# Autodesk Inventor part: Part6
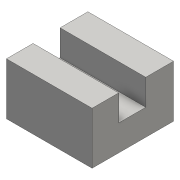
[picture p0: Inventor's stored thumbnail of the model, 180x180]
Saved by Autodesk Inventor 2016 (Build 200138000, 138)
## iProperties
Created: 2015-07
Part Number: Part6
Material: Generic
Document SubType Name: Modeling
Designer: Sandeep
Density: 1 g/cm^3
Appearance: Default
Author: Sandeep
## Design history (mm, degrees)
sketch "Sketch1"
  geometry: L1 (-17.042, 14.133)-(12.609, 14.133); L2 (12.609, 14.133)-(12.609, -14.063); L3 (12.609, -14.063)-(-17.042, -14.063); L4 (-17.042, -14.063)-(-17.042, 14.133); 1 further point
  constraints: 8 end point, 2 parallel, 1 horizontal, 1 perpendicular
extrude "Extrusion1" new body sketch "Sketch1" distance "d0" = 18; taper "d1" = 0 deg
sketch "Sketch2"
  geometry: L1 (-18, 28.196)-(-18, 0) reference; L2 (-18, 9.203)-(-9, 9.203); L3 (-9, 9.203)-(-9, 18.574); L4 (-9, 18.574)-(-18, 18.574); L5 (-18, 18.574)-(-18, 9.203); 1 further point
  constraints: 8 end point, 2 parallel, 1 horizontal, 1 perpendicular, 1 point on line
extrude "Extrusion2" cut sketch "Sketch2" distance "d2" = 8; taper "d3" = 0 deg
node "Direct Edit1"
body "Solid1"
feature "Delete1"
